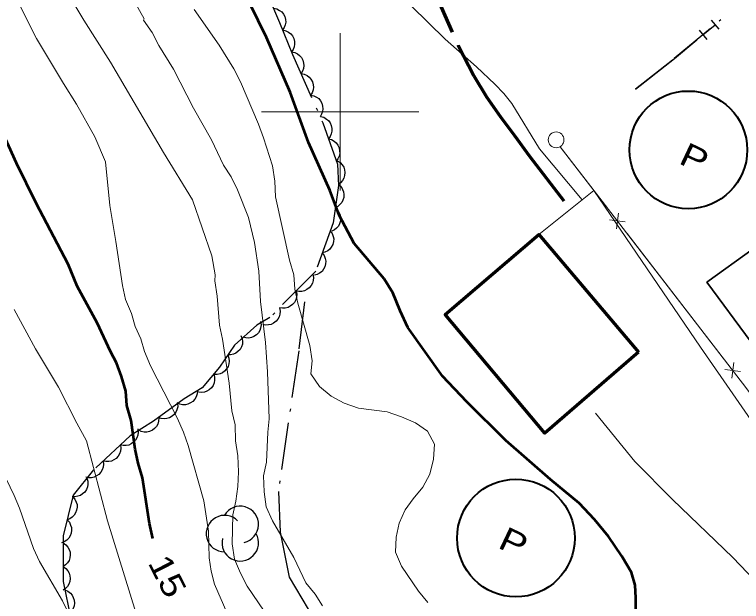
# Model space of a CAD drawing. Extents: x 356765 to 358572, y 5103174 to 5104650.
# Drawn here: x 357079.32 to 357125.5, y 5103868.9 to 5103906.19 of the extents above; entities that cross this region are included whole.
import ezdxf
from ezdxf.enums import TextEntityAlignment as Align

# ---------------------------------------------------------------- set-up
doc = ezdxf.new("R2010")
doc.units = 0
doc.header["$LTSCALE"] = 0.6
doc.linetypes.add('DOT_DASHED', pattern=[7.7, 5, -1.2, 0.3, -1.2])
doc.linetypes.add('LONG_DASHED', pattern=[7.5, 6, -1.5])
for name, color, linetype, lineweight in [('1', 7, 'Continuous', 53), ('19', 7, 'Continuous', 13), ('2', 7, 'Continuous', 13), ('22', 7, 'Continuous', 35), ('31', 7, 'Continuous', 70), ('36', 7, 'Continuous', 13), ('37', 7, 'Continuous', 13), ('38', 7, 'Continuous', 40), ('41', 7, 'DOT_DASHED', 25), ('44', 7, 'Continuous', 25), ('61', 7, 'Continuous', 13)]:
    doc.layers.add(name, color=color, linetype=linetype, lineweight=lineweight)

msp = doc.modelspace()

# ---------------------------------------------------------------- linework, layer by layer
at = {"layer": '1'}
for points in [[(357116.17, 5103874.11), (357115.18, 5103875.15), (357113.36, 5103876.65), (357110.52, 5103879.12), (357108.05, 5103881.58), (357106.51, 5103883.22), (357104.3, 5103886.31), (357103.81, 5103887.37), (357103.36, 5103888.5), (357102.79, 5103889.4), (357100.89, 5103891.64), (357099.93, 5103893.44), (357099.35, 5103895.04), (357097.99, 5103898.05), (357096.83, 5103901.25), (357095.33, 5103904.73), (357093.22, 5103909.04), (357092.05, 5103911.16), (357091.54, 5103912.72)], [(357088.1, 5103872.9), (357087.89, 5103873.85), (357087.44, 5103876.75), (357087.17, 5103877.69), (357086.98, 5103878.58), (357086.72, 5103880.4), (357086.45, 5103881.34), (357086.38, 5103882.26), (357086.11, 5103883.2), (357085.8, 5103884.06), (357085.41, 5103884.77), (357084.57, 5103886.61), (357083.29, 5103888.94), (357082.73, 5103890.32), (357080.68, 5103894.2), (357079.44, 5103896.74), (357078.26, 5103899.34), (357077.52, 5103901.16), (357077.11, 5103902.05), (357075.75, 5103904.65), (357074.64, 5103907.33)], [(357128.8, 5103839.21), (357128.41, 5103839.84), (357128.09, 5103840.54), (357127.85, 5103841.26), (357127.25, 5103843.51), (357126.99, 5103844.25), (357126.66, 5103845), (357124.37, 5103849.38), (357123.64, 5103850.92), (357122.79, 5103853.9), (357122.15, 5103855.44), (357121.42, 5103856.6), (357119.9, 5103858.81), (357119.16, 5103860.3), (357118.69, 5103862.62), (357118.6, 5103864.92), (357118.78, 5103868.05), (357118.79, 5103869.12), (357118.75, 5103869.93), (357118.52, 5103870.74), (357117.91, 5103871.77), (357117.05, 5103873.03), (357116.17, 5103874.11)]]:
    msp.add_lwpolyline(points, dxfattribs=at)
at = {"layer": '19'}
msp.add_line((357112.62, 5103892.21), (357116.12, 5103895.01), dxfattribs=at)
for points in [[(357133.29, 5103870.56), (357130.98, 5103873.5), (357127.19, 5103878.84), (357122.9, 5103885.05), (357116.12, 5103895.01)], [(357126.8, 5103869.77), (357124.95, 5103871.68), (357121.12, 5103875.38), (357118.73, 5103877.79), (357116.22, 5103880.85)]]:
    msp.add_lwpolyline(points, dxfattribs=at)
at = {"layer": '2'}
for points in [[(357081.62, 5103909.34), (357083.72, 5103905.83), (357085.42, 5103903.16), (357088.77, 5103897.42), (357090.62, 5103894.42), (357091.85, 5103890.85), (357092.06, 5103889.65), (357092.04, 5103889.26), (357092.19, 5103888.3), (357092.34, 5103886.45), (357092.53, 5103885.56), (357092.95, 5103882.77), (357093.13, 5103881), (357093.33, 5103880.11), (357093.36, 5103879.11), (357093.51, 5103878.14), (357093.54, 5103877.14), (357093.5, 5103876.19), (357093.38, 5103875.27), (357093.18, 5103874.4), (357093.14, 5103872.56), (357093.29, 5103871.59), (357093.67, 5103870.69), (357094.1, 5103869.87), (357095.18, 5103868.28)], [(357087.13, 5103860.37), (357086.02, 5103862.24), (357084.8, 5103864.08), (357083.75, 5103866.05), (357082.37, 5103868.94), (357080.91, 5103871.43), (357080.51, 5103872.26), (357079.64, 5103874.82), (357079.3, 5103875.63), (357078.51, 5103877.26), (357077.27, 5103880.59), (357075.32, 5103884.38), (357074.23, 5103886.66), (357072.87, 5103888.66), (357072.43, 5103889.48), (357071.53, 5103891.32), (357070.7, 5103893.16), (357070.01, 5103895.01), (357068.48, 5103899.76), (357067.42, 5103902.5), (357066.19, 5103906.03), (357065.43, 5103907.78)], [(357092.8, 5103868.2), (357092.03, 5103870), (357091.8, 5103870.82), (357091.68, 5103871.67), (357091.64, 5103873.36), (357091.34, 5103875.3), (357090.34, 5103878.8), (357090.04, 5103879.66), (357089.65, 5103880.56), (357087.95, 5103883.87), (357087.57, 5103884.77), (357087.33, 5103885.58), (357086.98, 5103886.37), (357086.75, 5103887.19), (357086.37, 5103888.09), (357086.18, 5103888.98), (357085.76, 5103891.77), (357085.36, 5103894.05), (357085.09, 5103896.82), (357084.41, 5103898.42), (357083.26, 5103900.5), (357082.43, 5103901.8), (357080.72, 5103904.66), (357079.46, 5103907.16)], [(357094.18, 5103893.29), (357093.49, 5103895.05), (357093.07, 5103895.87), (357092.6, 5103896.62), (357091.82, 5103898.23), (357090.68, 5103900.24), (357089.41, 5103902.72), (357088.48, 5103904.22), (357088.05, 5103905.04), (357087.51, 5103905.84), (357087.55, 5103905.91), (357086.67, 5103907.52)], [(357115.38, 5103894.42), (357112.66, 5103897.65), (357110.92, 5103900.53), (357110.41, 5103901.18), (357109.84, 5103901.76), (357108.67, 5103902.87), (357106.67, 5103904.63), (357104.53, 5103906.73)], [(357105.57, 5103868.83), (357104.99, 5103869.55), (357103.9, 5103871.13), (357103.52, 5103872.03), (357103.57, 5103872.98), (357103.76, 5103873.86), (357104.14, 5103874.72), (357104.64, 5103875.42), (357105.25, 5103876.16), (357105.71, 5103876.98), (357105.94, 5103877.93), (357105.99, 5103878.88), (357105.56, 5103879.71), (357104.78, 5103880.24), (357103.91, 5103880.63), (357103, 5103880.94), (357101.17, 5103881.18), (357100.26, 5103881.49), (357099.43, 5103881.95), (357098.69, 5103882.56), (357098.15, 5103883.35), (357098.22, 5103884.19), (357098.07, 5103885.16), (357097.31, 5103887.84), (357097.12, 5103888.73), (357097.05, 5103889.65), (357096.78, 5103890.58), (357095.89, 5103894.61), (357095.85, 5103895.61), (357095.7, 5103896.57), (357095.13, 5103898.36), (357094.82, 5103899.22), (357093.68, 5103901.92), (357093.25, 5103902.74), (357092.32, 5103904.24), (357090.73, 5103906.5)], [(357098.88, 5103868.61), (357098.41, 5103869.36), (357097.83, 5103870.07), (357097.06, 5103871.68), (357095.7, 5103874.01), (357095.31, 5103874.91), (357095.17, 5103875.87), (357095.13, 5103876.87), (357095.33, 5103877.75), (357095.41, 5103879.66), (357095.49, 5103880.5), (357095.39, 5103883.49), (357095.25, 5103885.34), (357094.94, 5103887.96), (357094.84, 5103889.88), (357094.57, 5103891.7), (357094.18, 5103893.29)], [(357100.49, 5103839.57), (357100.11, 5103840.55), (357099.54, 5103843.26), (357098.89, 5103845.88), (357097.89, 5103848.92), (357097.04, 5103852.38), (357096.57, 5103853.82), (357096.03, 5103855.23), (357095.52, 5103856.19), (357094.08, 5103857.68), (357092.61, 5103859.48), (357091.22, 5103861.04), (357090.01, 5103862.6), (357088.66, 5103864.43), (357087.6, 5103866.6), (357087.02, 5103868.2), (357085.23, 5103874.02), (357083.89, 5103879.11), (357083.27, 5103880.22), (357082.11, 5103882.51), (357080.65, 5103884.94), (357079.3, 5103887.44)]]:
    msp.add_lwpolyline(points, dxfattribs=at)
at = {"layer": '22', "linetype": 'LONG_DASHED', "lineweight": 70}
msp.add_lwpolyline([(357105.67, 5103908.36), (357107.5, 5103904.23), (357108.49, 5103902.3), (357109.31, 5103900.96), (357110.18, 5103899.7), (357111.09, 5103898.51), (357112.03, 5103897.2), (357114.53, 5103893.95)], dxfattribs=at)
at = {"layer": '31'}
msp.add_lwpolyline([(357118.96, 5103884.73), (357113, 5103879.59), (357106.68, 5103887.13), (357112.62, 5103892.21), (357118.96, 5103884.73)], close=True, dxfattribs=at)
at = {"layer": '31', "lineweight": 35}
msp.add_lwpolyline([(357126.24, 5103891.3), (357129.14, 5103887.7), (357126.11, 5103885.38), (357123.31, 5103889.18), (357126.24, 5103891.3)], close=True, dxfattribs=at)
at = {"layer": '36'}
msp.add_circle((357113.7238, 5103898.2271), 0.5, dxfattribs=at)
at = {"layer": '37', "lineweight": 25}
for p, q in [((357123.58, 5103905.83), (357124.06, 5103905.25)), ((357123.05, 5103904.9), (357123.82, 5103905.54)), ((357122.81, 5103905.19), (357123.29, 5103904.61))]:
    msp.add_line(p, q, dxfattribs=at)
at = {"layer": '37'}
for p, q in [((357117, 5103893.87), (357113.98, 5103897.79)), ((357117.68, 5103893.57), (357117.55, 5103892.58)), ((357118.11, 5103893.01), (357117.12, 5103893.14)), ((357121.28, 5103888.32), (357118.23, 5103892.28)), ((357124.33, 5103884.36), (357121.28, 5103888.32)), ((357125.01, 5103884.07), (357124.88, 5103883.08)), ((357125.44, 5103883.51), (357124.45, 5103883.64))]:
    msp.add_line(p, q, dxfattribs=at)
at = {"layer": '37', "linetype": 'DOT_DASHED', "lineweight": 25}
msp.add_lwpolyline([(357118.76, 5103901.46), (357121.23, 5103903.41), (357124.18, 5103905.87)], dxfattribs=at)
at = {"layer": '37', "lineweight": 25}
msp.add_lwpolyline([(357118.77, 5103901.44), (357121.24, 5103903.39), (357122.66, 5103904.58)], dxfattribs=at)
at = {"layer": '37'}
msp.add_lwpolyline([(357186.05, 5103892.44), (357200.9, 5103875.12), (357198.46, 5103872.84), (357180.35, 5103858.53), (357167.68, 5103873.22), (357161.24, 5103880.71), (357160.24, 5103881.86), (357147.14, 5103870.09), (357146.92, 5103870.1), (357145.06, 5103870.17), (357133.97, 5103871.46), (357125.77, 5103882.5), (357113.98, 5103897.79)], dxfattribs=at)
at = {"layer": '38'}
for centre in [(357122.1252, 5103897.5907), (357111.1692, 5103872.9256)]:
    msp.add_circle(centre, 3.7394, dxfattribs=at)
at = {"layer": '41'}
msp.add_lwpolyline([(357097.73, 5103887.93), (357097.37, 5103884.82), (357096.08, 5103875.88), (357096.2, 5103873.29), (357096.77, 5103870.44), (357097.98, 5103868.41), (357099.23, 5103867.13), (357100.42, 5103866.46), (357101.84, 5103865.87), (357102.52, 5103865.68), (357105.72, 5103865.46), (357109.09, 5103865.88), (357112.5, 5103867.07), (357116.49, 5103864.04), (357121.6, 5103862.68), (357127.5, 5103863.44)], dxfattribs=at)
at = {"layer": '44', "linetype": 'DOT_DASHED'}
msp.add_lwpolyline([(357095.39, 5103907.49), (357096.15, 5103905.69), (357096.98, 5103903.66), (357098.9, 5103899.31), (357099.83, 5103896.68), (357099.89, 5103895.32), (357099.55, 5103892.96), (357098.46, 5103889.89), (357095.54, 5103886.94), (357094.71, 5103886.46), (357093.28, 5103885.18), (357092.33, 5103883.79), (357091.24, 5103882.47), (357090.09, 5103881.78), (357088.14, 5103880.35), (357086.67, 5103879.43), (357084.34, 5103877.27), (357083.03, 5103875.64), (357082.41, 5103873.07), (357082.4, 5103870.16), (357083, 5103867.3)], dxfattribs=at)
at = {"layer": '44'}
for points in [[(357095.77, 5103906.59), (357095.97, 5103906.55), (357096.15, 5103906.45), (357096.29, 5103906.36), (357096.4, 5103906.22), (357096.48, 5103906.06), (357096.53, 5103905.87), (357096.55, 5103905.71), (357096.51, 5103905.53), (357096.45, 5103905.36), (357096.35, 5103905.21)], [(357096.35, 5103905.21), (357096.55, 5103905.16), (357096.73, 5103905.07), (357096.86, 5103904.97), (357096.97, 5103904.83), (357097.05, 5103904.66), (357097.1, 5103904.48), (357097.11, 5103904.31), (357097.08, 5103904.14), (357097.01, 5103903.97), (357096.92, 5103903.82)], [(357096.91, 5103903.82), (357097.12, 5103903.78), (357097.3, 5103903.69), (357097.43, 5103903.59), (357097.54, 5103903.45), (357097.63, 5103903.29), (357097.68, 5103903.11), (357097.7, 5103902.95), (357097.67, 5103902.77), (357097.61, 5103902.6), (357097.52, 5103902.44)], [(357097.52, 5103902.44), (357097.72, 5103902.41), (357097.9, 5103902.31), (357098.04, 5103902.22), (357098.15, 5103902.08), (357098.24, 5103901.92), (357098.28, 5103901.73), (357098.31, 5103901.57), (357098.28, 5103901.4), (357098.22, 5103901.22), (357098.12, 5103901.07)], [(357098.12, 5103901.07), (357098.33, 5103901.03), (357098.51, 5103900.94), (357098.64, 5103900.85), (357098.75, 5103900.71), (357098.84, 5103900.55), (357098.89, 5103900.36), (357098.91, 5103900.2), (357098.88, 5103900.03), (357098.82, 5103899.85), (357098.73, 5103899.7)], [(357098.76, 5103899.71), (357098.96, 5103899.66), (357099.13, 5103899.55), (357099.26, 5103899.45), (357099.36, 5103899.3), (357099.44, 5103899.14), (357099.47, 5103898.95), (357099.48, 5103898.78), (357099.44, 5103898.61), (357099.36, 5103898.44), (357099.26, 5103898.3)], [(357099.26, 5103898.3), (357099.46, 5103898.24), (357099.63, 5103898.14), (357099.76, 5103898.03), (357099.86, 5103897.89), (357099.94, 5103897.72), (357099.97, 5103897.53), (357099.98, 5103897.37), (357099.94, 5103897.2), (357099.86, 5103897.03), (357099.76, 5103896.88)], [(357099.82, 5103896.9), (357100, 5103896.79), (357100.13, 5103896.63), (357100.23, 5103896.5), (357100.28, 5103896.33), (357100.3, 5103896.15), (357100.28, 5103895.96), (357100.24, 5103895.8), (357100.15, 5103895.65), (357100.03, 5103895.5), (357099.89, 5103895.4)], [(357099.9, 5103895.4), (357100.06, 5103895.26), (357100.16, 5103895.08), (357100.22, 5103894.93), (357100.24, 5103894.75), (357100.23, 5103894.57), (357100.18, 5103894.39), (357100.11, 5103894.24), (357099.99, 5103894.11), (357099.85, 5103893.99), (357099.69, 5103893.91)], [(357099.69, 5103893.91), (357099.84, 5103893.77), (357099.95, 5103893.6), (357100.01, 5103893.44), (357100.03, 5103893.27), (357100.02, 5103893.09), (357099.96, 5103892.9), (357099.9, 5103892.75), (357099.78, 5103892.62), (357099.64, 5103892.51), (357099.47, 5103892.43)], [(357099.37, 5103892.45), (357099.49, 5103892.28), (357099.56, 5103892.09), (357099.6, 5103891.93), (357099.58, 5103891.76), (357099.53, 5103891.58), (357099.44, 5103891.41), (357099.35, 5103891.28), (357099.21, 5103891.17), (357099.04, 5103891.08), (357098.87, 5103891.04)], [(357098.87, 5103891.04), (357098.99, 5103890.87), (357099.06, 5103890.68), (357099.09, 5103890.52), (357099.08, 5103890.34), (357099.03, 5103890.16), (357098.94, 5103890), (357098.85, 5103889.86), (357098.7, 5103889.76), (357098.54, 5103889.67), (357098.37, 5103889.63)], [(357098.26, 5103889.69), (357098.3, 5103889.49), (357098.28, 5103889.28), (357098.24, 5103889.12), (357098.16, 5103888.97), (357098.04, 5103888.83), (357097.88, 5103888.72), (357097.74, 5103888.64), (357097.57, 5103888.6), (357097.38, 5103888.59), (357097.21, 5103888.62)], [(357097.21, 5103888.62), (357097.25, 5103888.42), (357097.23, 5103888.22), (357097.19, 5103888.06), (357097.1, 5103887.9), (357096.98, 5103887.76), (357096.83, 5103887.65), (357096.69, 5103887.57), (357096.51, 5103887.53), (357096.33, 5103887.53), (357096.15, 5103887.56)], [(357096.15, 5103887.56), (357096.19, 5103887.35), (357096.17, 5103887.15), (357096.13, 5103886.99), (357096.05, 5103886.84), (357095.93, 5103886.7), (357095.77, 5103886.58), (357095.63, 5103886.5), (357095.46, 5103886.47), (357095.27, 5103886.46), (357095.1, 5103886.49)], [(357094.95, 5103886.68), (357094.98, 5103886.47), (357094.95, 5103886.27), (357094.9, 5103886.11), (357094.81, 5103885.97), (357094.68, 5103885.83), (357094.52, 5103885.73), (357094.37, 5103885.66), (357094.2, 5103885.63), (357094.01, 5103885.64), (357093.84, 5103885.68)], [(357093.7, 5103885.8), (357093.78, 5103885.6), (357093.8, 5103885.4), (357093.79, 5103885.24), (357093.73, 5103885.07), (357093.64, 5103884.91), (357093.5, 5103884.77), (357093.38, 5103884.67), (357093.22, 5103884.6), (357093.04, 5103884.56), (357092.86, 5103884.56)], [(357092.86, 5103884.56), (357092.93, 5103884.36), (357092.95, 5103884.16), (357092.94, 5103884), (357092.88, 5103883.83), (357092.79, 5103883.67), (357092.66, 5103883.53), (357092.53, 5103883.43), (357092.37, 5103883.36), (357092.19, 5103883.32), (357092.01, 5103883.32)], [(357091.97, 5103883.35), (357092.03, 5103883.15), (357092.02, 5103882.95), (357092, 5103882.78), (357091.93, 5103882.62), (357091.82, 5103882.47), (357091.68, 5103882.35), (357091.54, 5103882.25), (357091.38, 5103882.2), (357091.19, 5103882.18), (357091.01, 5103882.19)], [(357090.93, 5103882.29), (357090.92, 5103882.08), (357090.85, 5103881.89), (357090.78, 5103881.74), (357090.65, 5103881.61), (357090.5, 5103881.51), (357090.33, 5103881.44), (357090.17, 5103881.39), (357089.99, 5103881.4), (357089.81, 5103881.44), (357089.65, 5103881.51)], [(357089.67, 5103881.48), (357089.68, 5103881.27), (357089.63, 5103881.07), (357089.57, 5103880.92), (357089.46, 5103880.78), (357089.32, 5103880.66), (357089.15, 5103880.57), (357088.99, 5103880.52), (357088.82, 5103880.51), (357088.63, 5103880.53), (357088.46, 5103880.59)], [(357088.48, 5103880.56), (357088.47, 5103880.35), (357088.41, 5103880.16), (357088.33, 5103880.01), (357088.21, 5103879.89), (357088.07, 5103879.78), (357087.89, 5103879.7), (357087.73, 5103879.66), (357087.56, 5103879.66), (357087.37, 5103879.7), (357087.21, 5103879.77)], [(357087.14, 5103879.86), (357087.17, 5103879.66), (357087.14, 5103879.46), (357087.09, 5103879.3), (357087, 5103879.15), (357086.88, 5103879.01), (357086.72, 5103878.91), (357086.57, 5103878.83), (357086.4, 5103878.8), (357086.21, 5103878.8), (357086.04, 5103878.84)], [(357086.04, 5103878.84), (357086.07, 5103878.64), (357086.04, 5103878.44), (357085.99, 5103878.28), (357085.9, 5103878.13), (357085.78, 5103877.99), (357085.62, 5103877.89), (357085.47, 5103877.81), (357085.3, 5103877.78), (357085.11, 5103877.78), (357084.94, 5103877.82)], [(357084.94, 5103877.82), (357084.97, 5103877.62), (357084.94, 5103877.42), (357084.89, 5103877.26), (357084.8, 5103877.11), (357084.68, 5103876.97), (357084.52, 5103876.87), (357084.37, 5103876.79), (357084.2, 5103876.76), (357084.01, 5103876.76), (357083.84, 5103876.8)], [(357083.91, 5103876.74), (357083.97, 5103876.54), (357083.97, 5103876.33), (357083.95, 5103876.17), (357083.88, 5103876.01), (357083.78, 5103875.85), (357083.63, 5103875.73), (357083.5, 5103875.63), (357083.33, 5103875.58), (357083.15, 5103875.55), (357082.97, 5103875.57)], [(357083.01, 5103875.55), (357083.15, 5103875.39), (357083.24, 5103875.21), (357083.29, 5103875.05), (357083.29, 5103874.88), (357083.26, 5103874.69), (357083.19, 5103874.52), (357083.11, 5103874.38), (357082.98, 5103874.26), (357082.82, 5103874.15), (357082.66, 5103874.09)], [(357082.66, 5103874.09), (357082.8, 5103873.94), (357082.88, 5103873.75), (357082.93, 5103873.59), (357082.94, 5103873.42), (357082.91, 5103873.24), (357082.84, 5103873.06), (357082.76, 5103872.92), (357082.63, 5103872.8), (357082.47, 5103872.69), (357082.3, 5103872.63)], [(357082.41, 5103872.62), (357082.58, 5103872.5), (357082.71, 5103872.34), (357082.79, 5103872.2), (357082.84, 5103872.03), (357082.85, 5103871.85), (357082.82, 5103871.66), (357082.78, 5103871.5), (357082.68, 5103871.35), (357082.55, 5103871.22), (357082.4, 5103871.12)], [(357082.4, 5103871.12), (357082.58, 5103871), (357082.7, 5103870.84), (357082.79, 5103870.7), (357082.83, 5103870.53), (357082.85, 5103870.35), (357082.82, 5103870.16), (357082.77, 5103870), (357082.67, 5103869.85), (357082.55, 5103869.72), (357082.4, 5103869.62)], [(357082.51, 5103869.63), (357082.7, 5103869.55), (357082.86, 5103869.42), (357082.98, 5103869.3), (357083.05, 5103869.15), (357083.11, 5103868.97), (357083.12, 5103868.78), (357083.1, 5103868.61), (357083.04, 5103868.45), (357082.94, 5103868.29), (357082.82, 5103868.16)]]:
    msp.add_lwpolyline(points, dxfattribs=at)
for centre, start, end in [((357093.6548, 5103873.7867), 282.26917, 149.72626), ((357092.6566, 5103873.2064), 44.11537, 269.80396), ((357093.6548, 5103872.626), 166.93686, 29.62122)]:
    msp.add_arc(centre, 1.1608, start, end, dxfattribs=at)
at = {"layer": '61'}
for p, q in [((357100, 5103895), (357100, 5103905)), ((357095, 5103900), (357105, 5103900))]:
    msp.add_line(p, q, dxfattribs=at)

# ---------------------------------------------------------------- texts
at = {"layer": '1', "width": 1.2}
msp.add_text('15', height=1.5, rotation=297.158, dxfattribs=at).set_placement((357088.367, 5103870.1673), align=Align.CENTER)
at = {"layer": '38', "width": 1.25}
for p in [(357121.44, 5103896.76), (357109.95, 5103872.34)]:
    msp.add_text('P', height=1.5, rotation=334.69, dxfattribs=at).set_placement(p)

doc.saveas('drawing.dxf')
